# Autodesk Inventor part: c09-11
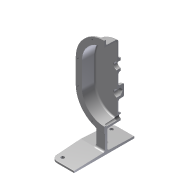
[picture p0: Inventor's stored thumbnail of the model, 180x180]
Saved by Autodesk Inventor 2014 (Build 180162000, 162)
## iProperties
Created: 2010-12
Part Number: c09-11
Document SubType Name: Modeling
Designer: Thom Tremblay
Density: 7.25 g/cm^3
Material: Iron, Cast
Mass: 1233.53 g
Surface Area: 883.619 cm^2
Volume: 170.142 cm^3
Appearance: Steel
Author: Thom Tremblay
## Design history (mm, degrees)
sketch "Sketch1"
  geometry: L1 (-50, -50)-(-50, 0); L2 (50, 0)-(50, -50); L3 (-60, 0)-(-60, -50); L4 (60, -50)-(60, 0); A1 r 50 centre (0, 0) between (50, 0) and (-50, 0); A2 r 50 centre (0, -50) between (-50, -50) and (50, -50); A3 r 60 centre (0, -50) between (-60, -50) and (60, -50); A4 r 60 centre (0, 0) between (60, 0) and (-60, 0); 1 further point
  constraints: 8 end point, 8 point on circle, 4 centre point, 4 tangent, 2 parallel, 1 coincident, 1 vertical, 3 other
  dimensions: "d0" = 50 distance of L2.start L2.end; "d1" = 50 radius of A1; "d2" = 10 radial gap between concentric circles of A4 A1
extrude "Extrusion1" new body sketch "Sketch1" distance "d3" = 30; taper "d4" = -2 deg
fillet "Fillet1" dims "d7" = 6
shell "Shell3" dims "d132" = 3
extrude "Extrusion2" join sketch "Sketch1" distance "d5" = 4; taper "d6" = -2 deg
fillet "Fillet12" dims "d133" = 2
fillet "Fillet13" dims "d134" = 1
workplane "Work Plane2"
sketch "Sketch7"
  geometry: C1 r 7.5 at (0, -95); 1 further point
  constraints: 1 centre point, 1 vertical alignment
  dimensions: "d64" = 15 diameter of C1; "d65" = 95 distance of point (0, 0) C1.centre
extrude "Extrusion8" join sketch "Sketch7" stored distance "d66" = 12.7; taper "d67" = 2 deg
fillet "Fillet2" dims "d9" = 3, "d10" = 1
hole "Hole3" diameter "d70" = 8; stored, may be unused: countersink angle "d74" = 82 deg, drill point angle "d76" = 118 deg; dims "d68" = 10, "d69" = 10, "d71" = 9, "d72" = 9.525, "d73" = 6.35, "d75" = 30, "d77" = 0.62479, "d78" = 7.985
workplane "Work Plane1"
sketch "Sketch2"
  geometry: L1 (-20.917, -1.5)-(20.917, -1.5); L2 (20.917, -1.5)-(20.219, -21.5); L3 (20.219, -21.5)-(16.219, -21.5); L4 (16.219, -21.5)-(15.695, -6.5); L5 (15.695, -6.5)-(-15.695, -6.5); L6 (-15.695, -6.5)-(-16.219, -21.5); L7 (-16.219, -21.5)-(-20.219, -21.5); L8 (-20.219, -21.5)-(-20.917, -1.5); L9 (-16.219, -21.5)-(16.219, -21.5); 3 further points
  constraints: 18 end point, 3 parallel, 2 equal length, 2 midpoint, 2 vertical alignment, 1 collinear, 1 horizontal
  dimensions: "d12" = 4 deg angle of L8 L6; "d13" = 88 deg angle of L8 L1; "d14" = 1.5 distance from line of point (0, 0) L1; "d15" = 20 vertical distance of L1.end L2.end; "d16" = 4 distance of L2.end L3.end; "d17" = 5 distance between parallel lines of L1 L5
extrude "Extrusion3" join sketch "Sketch2" stored distance "d18" = 27.94; taper "d19" = 0 deg
sketch "Sketch3"
  geometry: L1 (-70, -150)-(70, -150) reference; L2 (-50, -150)-(50, -150); L3 (50, -150)-(50, -144); L4 (50, -144)-(-50, -144); L5 (-50, -144)-(-50, -150); 2 further points
  constraints: 8 end point, 2 parallel, 1 horizontal, 1 midpoint, 1 perpendicular, 1 point on line, 1 vertical alignment
  dimensions: "d20" = 100 distance of L3.end L4.end; "d21" = 6 distance of L2.end L3.end
extrude "Extrusion4" join sketch "Sketch3" distance "d22" = 63.5; taper "d23" = 0 deg
feature "FaceDraft1" dims angle "d24" = 2 deg
sketch "Sketch4"
  geometry: L1 (-50, -150)-(50, -150) reference; L2 (50, -150)-(50, -143.773) reference; L3 (50, -143.773)-(-50, -143.773) reference; L4 (-50, -143.773)-(-50, -150) reference; 1 further point
extrude "Extrusion5" join sketch "Sketch4" distance "d25" = 63.5; taper "d26" = 0 deg
feature "FaceDraft2" dims angle "d27" = 2 deg
fillet "Fillet3" dims "d28" = 12
fillet "Fillet4"
fillet "Fillet5"
fillet "Fillet6" dims "d29" = 4
fillet "Fillet7" dims "d30" = 4
fillet "Fillet8" dims "d31" = 2
sketch "Sketch5"
  geometry: C1 r 12.5 at (0, 0); 1 further point
  constraints: 1 centre point, 1 coincident
  dimensions: "d32" = 25 diameter of C1
extrude "Extrusion6" join sketch "Sketch5" distance "d33" = 5; taper "d35" = -2 deg; dims "d34" = 8, "d36" = -2 deg
hole "Hole1" diameter "d40" = 14; stored, may be unused: countersink angle "d44" = 82 deg, drill point angle "d46" = 118 deg; dims "d38" = 10, "d39" = 10, "d41" = 19.05, "d42" = 9.525, "d43" = 6.35, "d45" = 25.4
sketch "Sketch10"
  geometry: C1 r 12.5 at (0, -50); A1 r 60 centre (0, -50) between (-60, -50) and (-18.704, -107.01) reference; 1 further point
  constraints: 1 centre point, 1 coincident
  dimensions: "d135" = 25 diameter of C1
extrude "Extrusion9" join sketch "Sketch10" distance "d136" = 12; taper "d137" = -2 deg
fillet "Fillet9" dims "d37" = 3
hole "Hole2" diameter "d55" = 14; stored, may be unused: countersink angle "d59" = 82 deg, drill point angle "d61" = 118 deg; dims "d53" = 10, "d54" = 10, "d56" = 19.05, "d57" = 9.525, "d58" = 6.35, "d60" = 8
hole "Hole4" diameter "d81" = 7; stored, may be unused: countersink angle "d85" = 82 deg, drill point angle "d87" = 118 deg; dims "d79" = 10, "d80" = 10, "d82" = 12.7, "d83" = 12.8778, "d84" = 6.35, "d86" = 30.48
hole "Hole5" diameter "d90" = 7; stored, may be unused: countersink angle "d94" = 82 deg, drill point angle "d96" = 118 deg; dims "d88" = 10, "d89" = 10, "d91" = 12.7, "d92" = 12.8778, "d93" = 6.35, "d95" = 30.48
hole "Hole6" diameter "d99" = 7; stored, may be unused: countersink angle "d103" = 82 deg, drill point angle "d105" = 118 deg; dims "d97" = 10, "d98" = 10, "d100" = 12.7, "d101" = 12.8778, "d102" = 6.35, "d104" = 30.48
hole "Hole7" diameter "d108" = 7; stored, may be unused: countersink angle "d112" = 82 deg, drill point angle "d114" = 118 deg; dims "d106" = 10, "d107" = 10, "d109" = 12.7, "d110" = 12.8778, "d111" = 6.35, "d113" = 30.48
fillet "Fillet11" dims "d122" = 1
node "Hole10"
chamfer "Chamfer1" distance "d138" = 0.6; stored, may be unused: second distance "d139" = 2, angle "d140" = 45 deg
split "Split1"
body "Solid1"
node "Projected Loop1"
sketch "Sketch9"
  geometry: 8 further points
hole "Hole9" sketch "Sketch9" diameter "d123" = 3.242; stored, may be unused: countersink angle "d127" = 82 deg, drill point angle "d129" = 0 deg; dims "d124" = 19.05, "d125" = 9.525, "d126" = 6.35, "d128" = 25.4
other parameters: "d63" = -35
